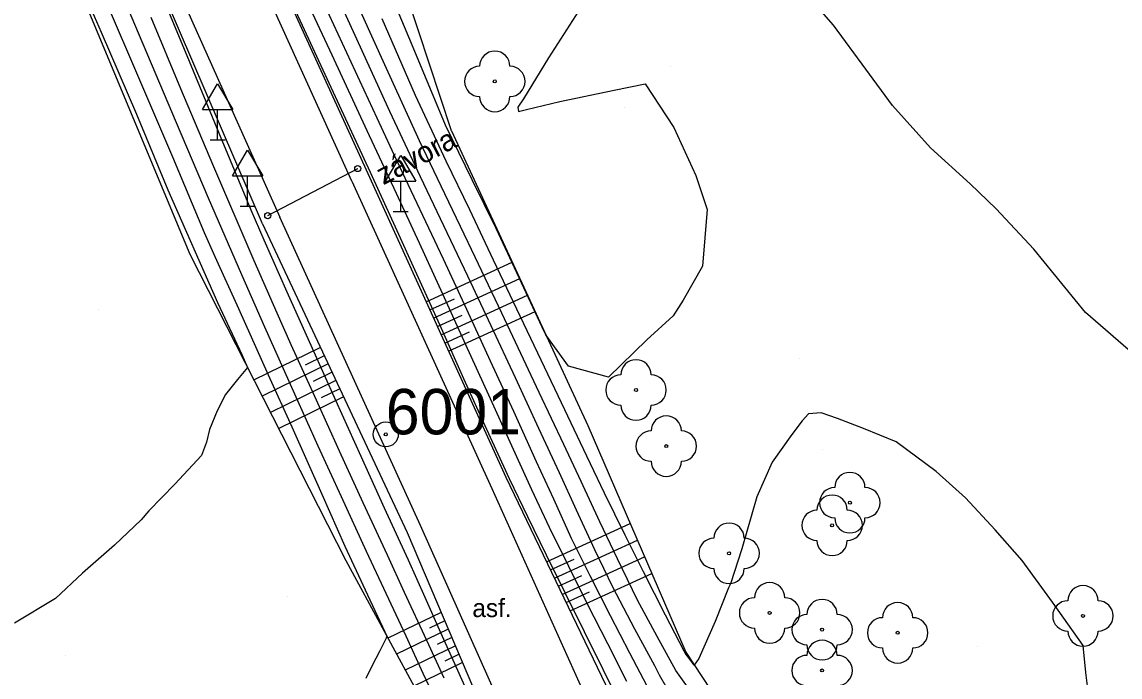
# Model space of a CAD drawing. Extents: x -448957 to -448612, y -1107690 to -1107245.
# Drawn here: x -448777.15 to -448740.89, y -1107367.47 to -1107345.84 of the extents above; entities that cross this region are included whole.
import ezdxf

# ---------------------------------------------------------------- set-up
doc = ezdxf.new("R2010")
doc.units = 0
for name, color, linetype in [('22', 7, 'Continuous'), ('34', 7, 'Continuous'), ('63', 7, 'Continuous'), ('Default', 7, 'Continuous'), ('Vrstva 1', 7, 'Continuous'), ('Vrstva 10', 7, 'Continuous'), ('Vrstva 14', 7, 'Continuous'), ('Vrstva 15', 7, 'Continuous'), ('Vrstva 16', 7, 'Continuous'), ('Vrstva 17', 7, 'Continuous'), ('Vrstva 22', 7, 'Continuous'), ('Vrstva 33', 7, 'Continuous'), ('Vrstva 34', 7, 'Continuous'), ('Vrstva 40', 7, 'Continuous'), ('Vrstva 42', 7, 'Continuous'), ('Vrstva 63', 7, 'Continuous')]:
    doc.layers.add(name, color=color, linetype=linetype)

# ---------------------------------------------------------------- blocks, each defined once
blk = doc.blocks.new('DZ$0')
at = {"layer": '34'}
for p, q in [((-5, 10), (0, 18.5)), ((0, 18.5), (5, 10)), ((-5, 10), (5, 10)), ((0, 0), (0, 10)), ((-2.49, 0), (2.49, 0))]:
    blk.add_line(p, q, dxfattribs=at)
blk = doc.blocks.new('STROM$5')
at = {"layer": '22'}
blk.add_circle((0, 0), 0.5, dxfattribs=at)
for centre, start, end in [((0, 5), 0, 180), ((-5, 0), 90, 270), ((5, 0), 270, 90), ((0, -5), 180, 0)]:
    blk.add_arc(centre, 5, start, end, dxfattribs=at)
blk = doc.blocks.new('POINT_DISPLAY')
at = {"layer": 'Default'}
blk.add_line((0, 0), (0, 0), dxfattribs=at)
blk = doc.blocks.new('PPBP$7')
at = {"layer": '63'}
for radius in [4.12, 0.5]:
    blk.add_circle((0, 0), radius, dxfattribs=at)

msp = doc.modelspace()

# ---------------------------------------------------------------- linework, layer by layer
at = {"layer": 'Vrstva 10'}
for p, q in [((-448766.256, -1107351.1), (-448773.126, -1107335.921)), ((-448775.459, -1107337.053), (-448768.634, -1107352.287)), ((-448766.256, -1107351.1), (-448761.632, -1107361.251)), ((-448763.989, -1107362.47), (-448768.634, -1107352.287)), ((-448761.632, -1107361.251), (-448758.207, -1107368.874)), ((-448759.419, -1107372.726), (-448763.989, -1107362.47))]:
    msp.add_line(p, q, dxfattribs=at)
at = {"layer": 'Vrstva 14'}
for p, q in [((-448762.972, -1107349.433), (-448768.225, -1107333.452)), ((-448772.59, -1107335.779), (-448765.734, -1107350.847)), ((-448769.209, -1107352.504), (-448775.798, -1107337.169)), ((-448777.845, -1107338.519), (-448771.602, -1107353.511)), ((-448762.972, -1107349.433), (-448758.467, -1107359.167)), ((-448765.734, -1107350.847), (-448761.169, -1107360.877)), ((-448769.209, -1107352.504), (-448764.434, -1107362.701)), ((-448771.602, -1107353.511), (-448766.451, -1107363.624)), ((-448758.467, -1107359.167), (-448755.235, -1107366.651)), ((-448761.169, -1107360.877), (-448757.551, -1107368.4)), ((-448764.434, -1107362.701), (-448761.218, -1107370.239)), ((-448766.451, -1107363.624), (-448762.584, -1107370.769)), ((-448755.235, -1107366.651), (-448751.24, -1107372.666))]:
    msp.add_line(p, q, dxfattribs=at)
at = {"layer": 'Vrstva 15'}
for p, q in [((-448763.807, -1107355.08), (-448760.963, -1107353.775)), ((-448763.559, -1107355.626), (-448760.711, -1107354.319)), ((-448763.683, -1107355.353), (-448762.869, -1107354.98)), ((-448763.31, -1107356.173), (-448760.459, -1107354.864)), ((-448763.062, -1107356.719), (-448760.207, -1107355.408)), ((-448763.434, -1107355.899), (-448762.62, -1107355.526)), ((-448763.186, -1107356.446), (-448762.37, -1107356.071)), ((-448767.294, -1107356.593), (-448769.486, -1107357.664)), ((-448767.167, -1107356.865), (-448767.793, -1107357.171)), ((-448767.04, -1107357.137), (-448769.214, -1107358.199)), ((-448766.912, -1107357.408), (-448767.534, -1107357.712)), ((-448766.785, -1107357.68), (-448768.942, -1107358.734)), ((-448766.658, -1107357.952), (-448767.274, -1107358.253)), ((-448766.531, -1107358.223), (-448768.669, -1107359.269)), ((-448759.828, -1107363.665), (-448757.068, -1107362.406)), ((-448759.568, -1107364.206), (-448756.83, -1107362.957)), ((-448759.698, -1107363.936), (-448758.916, -1107363.579)), ((-448759.308, -1107364.747), (-448756.592, -1107363.508)), ((-448759.438, -1107364.477), (-448758.662, -1107364.123)), ((-448759.048, -1107365.288), (-448756.354, -1107364.059)), ((-448759.178, -1107365.017), (-448758.408, -1107364.666)), ((-448763.308, -1107365.34), (-448765.064, -1107366.187)), ((-448763.073, -1107365.892), (-448764.778, -1107366.715)), ((-448763.19, -1107365.616), (-448763.692, -1107365.858)), ((-448762.955, -1107366.168), (-448763.442, -1107366.404)), ((-448762.837, -1107366.445), (-448764.492, -1107367.243)), ((-448762.601, -1107366.997), (-448764.206, -1107367.772)), ((-448762.719, -1107366.721), (-448763.192, -1107366.949))]:
    msp.add_line(p, q, dxfattribs=at)
at = {"layer": 'Vrstva 16'}
for points in [[(-448774.223, -1107344.036), (-448773.162, -1107346.563), (-448772.059, -1107349.163), (-448771.001, -1107351.655), (-448769.904, -1107354.182), (-448769.138, -1107355.907), (-448768.148, -1107358.122), (-448767.376, -1107359.843), (-448766.609, -1107361.513), (-448765.779, -1107363.32), (-448765.207, -1107364.545), (-448764.476, -1107366.116), (-448763.908, -1107367.342), (-448763.18, -1107368.896)], [(-448756.4, -1107367.989), (-448757.074, -1107366.681), (-448757.714, -1107365.456), (-448758.385, -1107364.135), (-448759, -1107362.897), (-448759.593, -1107361.596), (-448760.155, -1107360.363), (-448760.912, -1107358.709), (-448761.677, -1107357.04), (-448762.464, -1107355.339), (-448763.233, -1107353.675), (-448764.779, -1107350.4), (-448765.42, -1107349.018), (-448767.135, -1107345.317)]]:
    msp.add_lwpolyline(points, dxfattribs=at)
at = {"layer": 'Vrstva 17'}
for points in [[(-448757.236, -1107368.701), (-448757.962, -1107367.229), (-448758.578, -1107365.985), (-448759.214, -1107364.699), (-448759.828, -1107363.453), (-448760.449, -1107362.181), (-448761.054, -1107360.933), (-448761.796, -1107359.296), (-448762.555, -1107357.624), (-448763.301, -1107355.969), (-448764.057, -1107354.294), (-448764.819, -1107352.621), (-448765.58, -1107350.955), (-448766.73, -1107348.463), (-448767.885, -1107345.959), (-448769.092, -1107343.356)], [(-448758.473, -1107345.011), (-448759.769, -1107347.023), (-448760.592, -1107348.386), (-448760.781, -1107348.657), (-448760.755, -1107348.801), (-448760.491, -1107348.738), (-448759.385, -1107348.474), (-448757.601, -1107348.09), (-448756.569, -1107347.891), (-448755.63, -1107349.327), (-448754.899, -1107350.914), (-448754.528, -1107352.036), (-448754.679, -1107353.902), (-448755.316, -1107355.028), (-448755.652, -1107355.549), (-448756.52, -1107356.343), (-448757.785, -1107357.573), (-448759.107, -1107357.214), (-448759.851, -1107356.177), (-448759.975, -1107355.918), (-448760.73, -1107354.297), (-448761.492, -1107352.663), (-448762.279, -1107351.059), (-448763.161, -1107349.247), (-448764.23, -1107346.688), (-448765.693, -1107343.19)], [(-448775.61, -1107343.7), (-448774.536, -1107346.185), (-448773.37, -1107348.886), (-448772.329, -1107351.384), (-448770.691, -1107355.112), (-448769.889, -1107356.822), (-448769.697, -1107357.251), (-448770.028, -1107357.644), (-448770.432, -1107358.146), (-448770.705, -1107358.687), (-448770.952, -1107359.298), (-448771.058, -1107359.716), (-448771.223, -1107360.156), (-448772.098, -1107361.109), (-448772.956, -1107361.987), (-448773.217, -1107362.278), (-448774.098, -1107363.122), (-448775.145, -1107364.039), (-448776.04, -1107364.882), (-448777.394, -1107365.691)], [(-448755.848, -1107367.854), (-448756.099, -1107367.41), (-448756.256, -1107367.105), (-448756.91, -1107365.89), (-448757.644, -1107364.509), (-448758.232, -1107363.279), (-448758.841, -1107361.963), (-448759.405, -1107360.733), (-448760.082, -1107359.262), (-448760.855, -1107357.598), (-448761.658, -1107355.879), (-448762.427, -1107354.241), (-448763.217, -1107352.573), (-448763.985, -1107350.959), (-448765.001, -1107348.795), (-448766.15, -1107346.287), (-448767.291, -1107343.776)], [(-448757.18, -1107367.618), (-448757.807, -1107366.383), (-448758.475, -1107365.066), (-448759.093, -1107363.823), (-448759.73, -1107362.536), (-448760.31, -1107361.296), (-448760.97, -1107359.843), (-448761.731, -1107358.172), (-448762.49, -1107356.503), (-448763.253, -1107354.833), (-448764.027, -1107353.146), (-448764.788, -1107351.506), (-448765.75, -1107349.441), (-448766.908, -1107346.937), (-448768.114, -1107344.336)], [(-448772.691, -1107344.564), (-448771.624, -1107347.141), (-448770.657, -1107349.484), (-448769.595, -1107352.044), (-448769.166, -1107353.038), (-448768.403, -1107354.756), (-448767.566, -1107356.62), (-448766.798, -1107358.332), (-448765.965, -1107360.183), (-448765.185, -1107361.889), (-448764.402, -1107363.599), (-448763.846, -1107364.837), (-448763.331, -1107366.004), (-448762.773, -1107367.252), (-448762.265, -1107368.385)], [(-448755.067, -1107367.955), (-448755.556, -1107367.254), (-448756.175, -1107366.138), (-448756.826, -1107364.933), (-448757.484, -1107363.57), (-448758.066, -1107362.35), (-448758.691, -1107361.019), (-448759.261, -1107359.792), (-448760.069, -1107358.079), (-448760.85, -1107356.421), (-448761.309, -1107355.458), (-448762.078, -1107353.845), (-448762.419, -1107353.13), (-448763.191, -1107351.518), (-448764.027, -1107349.77), (-448765.164, -1107347.256), (-448766.285, -1107344.775)], [(-448740.294, -1107356.95), (-448742.039, -1107355.433), (-448743.741, -1107353.343), (-448744.979, -1107352.01), (-448745.848, -1107351.193), (-448747.147, -1107349.997), (-448748.403, -1107348.596), (-448749.291, -1107347.396), (-448750.351, -1107345.946), (-448751.527, -1107344.594)], [(-448774.363, -1107345.185), (-448773.302, -1107347.675), (-448772.183, -1107350.3), (-448771.129, -1107352.793), (-448770.78, -1107353.588), (-448770, -1107355.307), (-448769.017, -1107357.495), (-448768.242, -1107359.216), (-448767.253, -1107361.431), (-448766.483, -1107363.152), (-448765.735, -1107364.76), (-448765.163, -1107365.984), (-448765.098, -1107366.125), (-448765.129, -1107366.194), (-448765.33, -1107366.609), (-448765.592, -1107367.113), (-448765.793, -1107367.528)], [(-448772.888, -1107345.689), (-448771.918, -1107348.037), (-448770.859, -1107350.536), (-448769.492, -1107353.722), (-448768.732, -1107355.449), (-448768.269, -1107356.496), (-448767.492, -1107358.205), (-448766.671, -1107360.004), (-448765.889, -1107361.71), (-448765.093, -1107363.442), (-448764.526, -1107364.669), (-448763.789, -1107366.262), (-448763.223, -1107367.496)], [(-448741.87, -1107368.553), (-448742.028, -1107367.321), (-448742.113, -1107366.438), (-448743.129, -1107364.999), (-448744.126, -1107363.621), (-448745.022, -1107362.616), (-448746.001, -1107361.558), (-448746.97, -1107360.69), (-448748.286, -1107359.71), (-448749.36, -1107359.264), (-448750.223, -1107358.935), (-448750.763, -1107358.748), (-448751.176, -1107358.786), (-448751.385, -1107359.017), (-448751.733, -1107359.467), (-448752.384, -1107360.377), (-448752.886, -1107361.519), (-448753.38, -1107363.237), (-448753.759, -1107364.392), (-448753.824, -1107364.527), (-448754.26, -1107365.641), (-448754.797, -1107366.859), (-448754.952, -1107367.078), (-448755.098, -1107366.887), (-448755.252, -1107366.682), (-448755.284, -1107366.624), (-448755.904, -1107365.427), (-448756.63, -1107363.997), (-448757.233, -1107362.79), (-448757.917, -1107361.401), (-448758.498, -1107360.181), (-448759.23, -1107358.649), (-448760.007, -1107357.015), (-448760.813, -1107355.33), (-448761.575, -1107353.713), (-448762.365, -1107352.046), (-448763.146, -1107350.439), (-448764.154, -1107348.27), (-448765.259, -1107345.734)]]:
    msp.add_lwpolyline(points, dxfattribs=at)
at = {"layer": 'Vrstva 33'}
msp.add_line((-448769.032, -1107352.239), (-448766.063, -1107350.686), dxfattribs=at)
for centre in [(-448766.063, -1107350.686), (-448769.032, -1107352.239)]:
    msp.add_circle(centre, 0.1, dxfattribs=at)

# ---------------------------------------------------------------- block references
at = {"layer": 'Vrstva 1', "xscale": 0.1, "yscale": 0.10000000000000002}
for p in [(-448762.972, -1107349.433), (-448766.063, -1107350.686), (-448765.734, -1107350.847), (-448766.256, -1107351.1), (-448769.209, -1107352.504), (-448769.032, -1107352.239), (-448768.634, -1107352.287), (-448771.602, -1107353.511), (-448761.169, -1107360.877), (-448761.632, -1107361.251), (-448763.989, -1107362.47), (-448764.434, -1107362.701), (-448766.451, -1107363.624), (-448755.235, -1107366.651)]:
    msp.add_blockref('POINT_DISPLAY', p, dxfattribs=at)
at = {"layer": 'Vrstva 14', "xscale": 0.1, "yscale": 0.10000000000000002}
for p in [(-448755.722, -1107347.327), (-448757.268, -1107348.66), (-448774.629, -1107355.348), (-448751.466, -1107356.966), (-448758.467, -1107359.167), (-448750.714, -1107359.952), (-448768.385, -1107364.826), (-448745.611, -1107366.477), (-448775.721, -1107366.774)]:
    msp.add_blockref('POINT_DISPLAY', p, dxfattribs=at)
at = {"layer": 'Vrstva 22', "xscale": 0.1, "yscale": 0.10000000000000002}
for p in [(-448761.537, -1107347.805), (-448756.875, -1107357.996), (-448755.877, -1107359.849), (-448749.815, -1107361.717), (-448750.4, -1107362.465), (-448753.803, -1107363.389), (-448752.463, -1107365.357), (-448742.119, -1107365.456), (-448750.731, -1107365.91), (-448748.236, -1107366.014), (-448750.732, -1107367.258)]:
    msp.add_blockref('STROM$5', p, dxfattribs=at)
at = {"layer": 'Vrstva 34', "xscale": 0.1, "yscale": 0.10000000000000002}
for p in [(-448770.687, -1107349.732), (-448769.698, -1107351.926), (-448764.643, -1107352.097)]:
    msp.add_blockref('DZ$0', p, dxfattribs=at)
at = {"layer": 'Vrstva 63', "xscale": 0.1, "yscale": 0.10000000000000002}
msp.add_blockref('PPBP$7', (-448765.136, -1107359.461), dxfattribs=at)

# ---------------------------------------------------------------- texts
at = {"layer": 'Vrstva 40'}
msp.add_text('asf.', height=0.6, dxfattribs=at).set_placement((-448762.277, -1107365.495))
at = {"layer": 'Vrstva 42'}
msp.add_text('závora', height=0.7, rotation=27.6128, dxfattribs=at).set_placement((-448765.221, -1107351.241))
at = {"layer": 'Vrstva 63'}
msp.add_text('6001', height=1.5, dxfattribs=at).set_placement((-448765.136, -1107359.461))

doc.saveas('drawing.dxf')
